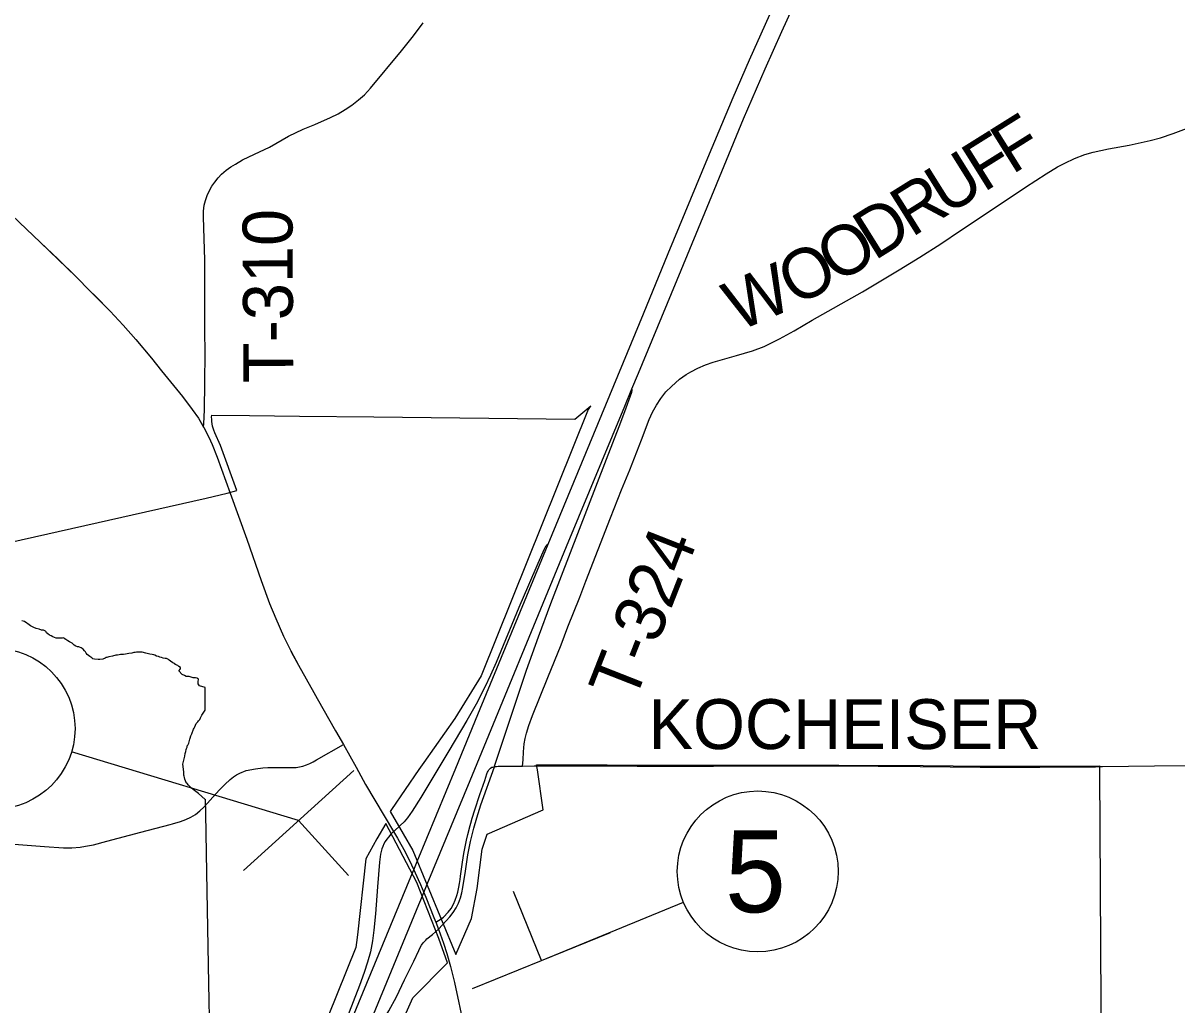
# Model space of a CAD drawing. Extents: x 40529 to 41139, y 15164 to 15584.
# Drawn here: x 40638.96 to 40678.43, y 15450.19 to 15483.78 of the extents above; entities that cross this region are included whole.
import ezdxf

# ---------------------------------------------------------------- set-up
doc = ezdxf.new("R2010")
doc.units = 0
for name, color, linetype in [('Default', 7, 'Continuous'), ('GM_X_Corporation', 7, 'Continuous'), ('GM_X_Interchange_Ramps', 7, 'Continuous'), ('GM_X_Interstate_Route', 7, 'Continuous'), ('GM_X_State_Route', 7, 'Continuous'), ('GM_X_Township_Road', 7, 'Continuous'), ('GM_X_Township_Road_Text', 7, 'Continuous'), ('SH_Data', 7, 'Continuous'), ('SH_Text', 7, 'Continuous')]:
    doc.layers.add(name, color=color, linetype=linetype)

msp = doc.modelspace()

# ---------------------------------------------------------------- linework, layer by layer
at = {"layer": 'Default'}
for p, q in [((40650.273, 15458.215), (40646.495, 15454.795)), ((40648.384, 15456.505), (40650.094, 15454.616)), ((40656.692, 15451.71), (40655.736, 15454.072)), ((40654.33, 15450.755), (40659.054, 15452.666))]:
    msp.add_line(p, q, dxfattribs=at)
at = {"layer": 'GM_X_Corporation'}
for points in [[(40636.703, 15465.612), (40641.064, 15466.592), (40645.217, 15467.526), (40645.936, 15467.698), (40646.266, 15467.787), (40645.71, 15469.328), (40645.521, 15469.763), (40645.486, 15469.849), (40645.462, 15469.922), (40645.442, 15469.997), (40645.427, 15470.073), (40645.416, 15470.149), (40645.41, 15470.226), (40645.408, 15470.303), (40645.409, 15470.372), (40646.701, 15470.358), (40648.408, 15470.339), (40650.952, 15470.311), (40657.836, 15470.236), (40658.382, 15470.685), (40658.362, 15470.659), (40658.289, 15470.562), (40654.63, 15461.454), (40653.728, 15459.986), (40652.668, 15458.491), (40652.612, 15458.411), (40652.497, 15458.244), (40651.558, 15456.884), (40651.516, 15456.806), (40651.958, 15456.045), (40652.287, 15455.479), (40653.766, 15451.922), (40654.181, 15452.883), (40654.295, 15453.146), (40654.49, 15454.177), (40654.657, 15455.523), (40654.837, 15456.038), (40656.747, 15456.867), (40656.558, 15458.233), (40656.521, 15458.402), (40656.787, 15458.404), (40658.001, 15458.405), (40658.935, 15458.404), (40660.055, 15458.399), (40662.669, 15458.396), (40664.805, 15458.4), (40666.858, 15458.399), (40669.747, 15458.387), (40671.796, 15458.362), (40673.846, 15458.359), (40675.779, 15458.376), (40675.78, 15458.189), (40675.845, 15446.277)], [(40645.447, 15443.901), (40645.314, 15450.925), (40645.241, 15454.724), (40645.203, 15456.743), (40645.194, 15457.227), (40645.189, 15457.221), (40644.958, 15457.428), (40644.817, 15457.533), (40644.719, 15457.61), (40644.685, 15457.638), (40644.617, 15457.706), (40644.574, 15457.767), (40644.537, 15457.794), (40644.533, 15457.802), (40644.511, 15457.86), (40644.492, 15457.919), (40644.482, 15457.973), (40644.467, 15458.02), (40644.461, 15458.054), (40644.458, 15458.164), (40644.427, 15458.43), (40644.491, 15458.705), (40644.498, 15458.798), (40644.523, 15458.862), (40644.536, 15458.933), (40644.546, 15458.96), (40644.566, 15459.011), (40644.57, 15459.054), (40644.591, 15459.08), (40644.623, 15459.145), (40644.661, 15459.286), (40644.674, 15459.317), (40644.693, 15459.4), (40644.728, 15459.467), (40644.792, 15459.621), (40644.811, 15459.661), (40644.837, 15459.708), (40644.882, 15459.816), (40644.884, 15459.83), (40644.897, 15459.844), (40644.933, 15459.875), (40644.96, 15459.912), (40645.002, 15459.96), (40645.031, 15460.016), (40645.077, 15460.103), (40645.18, 15460.279), (40645.184, 15461.057), (40644.988, 15461.104), (40644.946, 15461.182), (40644.948, 15461.271), (40644.958, 15461.315), (40644.96, 15461.332), (40644.958, 15461.342), (40644.925, 15461.359), (40644.911, 15461.368), (40644.901, 15461.368), (40644.856, 15461.379), (40644.837, 15461.38), (40644.776, 15461.381), (40644.674, 15461.416), (40644.642, 15461.425), (40644.6, 15461.426), (40644.534, 15461.432), (40644.48, 15461.464), (40644.403, 15461.491), (40644.282, 15461.619), (40644.339, 15461.69), (40644.34, 15461.712), (40644.338, 15461.731), (40644.287, 15461.772), (40644.254, 15461.807), (40644.159, 15461.838), (40644.158, 15461.862), (40644.08, 15461.896), (40643.994, 15461.958), (40643.955, 15461.992), (40643.928, 15462.009), (40643.862, 15462.045), (40643.819, 15462.047), (40643.745, 15462.054), (40643.687, 15462.074), (40643.637, 15462.091), (40643.587, 15462.109), (40643.524, 15462.126), (40643.467, 15462.154), (40643.431, 15462.165), (40643.367, 15462.177), (40643.293, 15462.194), (40643.205, 15462.217), (40643.153, 15462.228), (40643.027, 15462.26), (40642.888, 15462.263), (40642.838, 15462.259), (40642.789, 15462.253), (40642.751, 15462.246), (40642.681, 15462.229), (40642.577, 15462.214), (40642.462, 15462.193), (40642.388, 15462.185), (40642.336, 15462.184), (40642.292, 15462.179), (40642.242, 15462.169), (40642.182, 15462.163), (40642.131, 15462.161), (40642.013, 15462.124), (40641.893, 15462.097), (40641.819, 15462.078), (40641.801, 15462.077), (40641.762, 15462.051), (40641.682, 15462.025), (40641.581, 15462.015), (40641.524, 15462.013), (40641.404, 15462.016), (40641.345, 15462.034), (40641.306, 15462.062), (40641.236, 15462.115), (40641.194, 15462.145), (40641.144, 15462.177), (40641.109, 15462.23), (40641.089, 15462.267), (40641.062, 15462.303), (40641.008, 15462.358), (40640.973, 15462.386), (40640.947, 15462.408), (40640.889, 15462.436), (40640.86, 15462.443), (40640.818, 15462.445), (40640.758, 15462.463), (40640.709, 15462.495), (40640.683, 15462.526), (40640.661, 15462.542), (40640.637, 15462.566), (40640.592, 15462.589), (40640.546, 15462.613), (40640.492, 15462.644), (40640.456, 15462.67), (40640.421, 15462.697), (40640.365, 15462.733), (40640.346, 15462.752), (40640.308, 15462.743), (40640.247, 15462.737), (40640.091, 15462.74), (40639.97, 15462.786), (40639.913, 15462.814), (40639.859, 15462.845), (40639.802, 15462.883), (40639.763, 15462.926), (40639.742, 15462.956), (40639.721, 15462.976), (40639.695, 15462.993), (40639.651, 15463.008), (40639.585, 15463.017), (40639.507, 15463.046), (40639.403, 15463.072), (40639.328, 15463.1), (40639.215, 15463.166), (40639.122, 15463.227), (40639.088, 15463.257), (40639.009, 15463.305), (40638.917, 15463.338)], [(40652.057, 15449.92), (40652.294, 15450.437), (40653.477, 15451.638), (40653.182, 15452.468), (40652.425, 15454.379), (40651.362, 15456.401), (40651.058, 15455.875), (40650.678, 15455.196), (40650.395, 15452.588), (40650.367, 15452.326), (40650.337, 15452.153), (40647.478, 15445.056)]]:
    msp.add_lwpolyline(points, dxfattribs=at)
at = {"layer": 'GM_X_Interchange_Ramps'}
for points in [[(40653.167, 15452.781), (40653.427, 15453.071), (40653.557, 15453.206), (40653.673, 15453.352), (40653.772, 15453.51), (40653.854, 15453.678), (40653.919, 15453.853), (40653.968, 15454.033), (40654.006, 15454.216), (40654.087, 15454.771), (40654.176, 15455.325), (40654.266, 15455.783), (40654.373, 15456.238), (40654.475, 15456.597), (40654.618, 15457.042), (40655.08, 15458.342), (40655.087, 15458.362), (40656.182, 15461.64), (40656.584, 15462.787), (40657.009, 15463.924), (40658.918, 15468.859), (40659.347, 15469.976), (40659.543, 15470.492), (40659.777, 15471.152), (40659.788, 15471.198), (40659.791, 15471.222), (40659.789, 15471.241), (40659.787, 15471.264)], [(40656.924, 15465.953), (40656.903, 15465.947), (40656.875, 15465.928), (40656.858, 15465.911), (40656.834, 15465.878), (40656.786, 15465.782), (40656.567, 15465.29), (40656.248, 15464.557), (40655.92, 15463.789), (40655.139, 15461.904), (40654.951, 15461.479), (40654.751, 15461.061), (40654.452, 15460.485), (40654.135, 15459.918), (40653.52, 15458.88), (40652.567, 15457.29), (40652.269, 15456.82), (40652.109, 15456.593), (40651.988, 15456.455), (40651.854, 15456.327), (40651.647, 15456.143), (40651.631, 15456.129)], [(40651.631, 15456.129), (40651.539, 15456.034), (40651.455, 15455.932), (40651.4, 15455.859), (40651.347, 15455.782), (40651.302, 15455.701), (40651.263, 15455.617), (40651.231, 15455.53), (40651.183, 15455.35), (40651.144, 15455.074), (40651.084, 15454.236), (40651.014, 15453.307), (40650.959, 15452.75), (40650.91, 15452.381), (40650.839, 15452.015), (40650.743, 15451.655), (40650.629, 15451.3), (40650.47, 15450.862), (40649.894, 15449.386)], [(40652.731, 15452.411), (40652.774, 15452.458), (40652.96, 15452.598), (40653.167, 15452.781)], [(40648.174, 15443.15), (40648.194, 15443.161), (40648.21, 15443.173), (40648.231, 15443.19), (40648.254, 15443.227), (40648.351, 15443.428), (40648.385, 15443.492), (40648.582, 15443.906), (40648.844, 15444.505), (40649.716, 15446.574), (40650.058, 15447.343), (40650.38, 15448.018), (40650.717, 15448.686), (40650.986, 15449.178), (40651.47, 15449.989), (40651.732, 15450.474), (40652.01, 15451.055), (40652.32, 15451.696), (40652.492, 15452.061), (40652.54, 15452.158), (40652.585, 15452.233), (40652.645, 15452.319), (40652.731, 15452.411)]]:
    msp.add_lwpolyline(points, dxfattribs=at)
at = {"layer": 'GM_X_Interstate_Route'}
msp.add_line((40652.497, 15453.627), (40652.565, 15453.793), dxfattribs=at)
for points in [[(40652.785, 15454.324), (40654.247, 15457.87), (40657.549, 15465.872), (40659.548, 15470.678), (40659.787, 15471.264), (40660.006, 15471.801), (40661.47, 15475.331), (40662.356, 15477.487), (40663.605, 15480.503), (40664.341, 15482.217), (40664.908, 15483.496), (40667.468, 15489.094)], [(40648.136, 15444.675), (40648.586, 15445.785), (40652.223, 15454.578), (40652.322, 15454.819), (40652.439, 15455.101), (40653.759, 15458.293), (40654.516, 15460.125), (40656.924, 15465.953), (40660.178, 15473.833), (40661.026, 15475.903), (40662.384, 15479.173), (40663.245, 15481.238), (40663.802, 15482.52), (40664.754, 15484.647)], [(40652.565, 15453.793), (40652.665, 15454.035), (40652.785, 15454.324)], [(40641.19, 15426.749), (40641.685, 15427.752), (40641.91, 15428.229), (40642.242, 15428.931), (40642.782, 15430.119), (40643.263, 15431.23), (40644.049, 15433.124), (40645.472, 15436.571), (40645.814, 15437.405), (40648.174, 15443.15), (40648.376, 15443.642), (40652.497, 15453.627)]]:
    msp.add_lwpolyline(points, dxfattribs=at)
at = {"layer": 'GM_X_State_Route'}
for p, q in [((40649.647, 15459.571), (40649.914, 15459.097)), ((40649.914, 15459.097), (40650.348, 15458.324))]:
    msp.add_line(p, q, dxfattribs=at)
for points in [[(40631.547, 15483.816), (40633.184, 15482.292), (40635.219, 15480.375), (40636.374, 15479.292), (40639.551, 15476.277), (40640.161, 15475.701), (40640.758, 15475.114), (40641.268, 15474.603)], [(40641.268, 15474.603), (40641.417, 15474.454), (40641.939, 15473.924), (40642.383, 15473.447), (40642.814, 15472.958), (40643.349, 15472.313), (40643.695, 15471.887)], [(40643.695, 15471.887), (40644.405, 15471.01), (40644.743, 15470.566), (40644.953, 15470.26), (40645.134, 15469.962), (40645.145, 15469.943), (40645.315, 15469.614), (40645.428, 15469.36), (40645.599, 15468.927), (40646.042, 15467.699)], [(40646.042, 15467.699), (40646.61, 15466.122), (40647.102, 15464.715), (40647.39, 15463.926), (40647.601, 15463.407), (40647.868, 15462.811), (40648.115, 15462.308), (40648.144, 15462.253)], [(40648.144, 15462.253), (40648.378, 15461.814), (40648.905, 15460.885)], [(40648.905, 15460.885), (40649.022, 15460.679), (40649.647, 15459.571)], [(40650.348, 15458.324), (40650.665, 15457.737), (40651.631, 15456.129)], [(40651.631, 15456.129), (40651.766, 15455.9), (40652.036, 15455.408), (40652.244, 15454.99), (40652.322, 15454.819), (40652.477, 15454.481), (40652.547, 15454.313)], [(40652.547, 15454.313), (40652.665, 15454.035), (40652.731, 15453.878), (40653.01, 15453.184), (40653.075, 15453.025)], [(40653.075, 15453.025), (40653.167, 15452.781), (40653.336, 15452.309), (40653.454, 15451.955), (40653.581, 15451.505), (40653.711, 15450.959), (40654.051, 15449.411), (40654.584, 15446.816), (40654.633, 15446.578), (40654.89, 15445.299), (40655.141, 15444.113), (40655.453, 15442.666)]]:
    msp.add_lwpolyline(points, dxfattribs=at)
at = {"layer": 'GM_X_Township_Road'}
for p, q in [((40649.914, 15459.097), (40650.348, 15458.324)), ((40656.046, 15458.366), (40656.436, 15458.37))]:
    msp.add_line(p, q, dxfattribs=at)
for points in [[(40645.153, 15470.315), (40645.166, 15470.546), (40645.174, 15471.476), (40645.184, 15472.502), (40645.174, 15473.248), (40645.173, 15474.827), (40645.17, 15475.666), (40645.139, 15476.775), (40645.129, 15477.155), (40645.134, 15477.347), (40645.154, 15477.554), (40645.193, 15477.712), (40645.258, 15477.885), (40645.322, 15478.033), (40645.415, 15478.196), (40645.514, 15478.339), (40645.632, 15478.482), (40645.746, 15478.61), (40645.909, 15478.748), (40646.069, 15478.857), (40646.224, 15478.959), (40646.464, 15479.098), (40646.876, 15479.296), (40647.384, 15479.538), (40648.034, 15479.91), (40648.538, 15480.149), (40648.943, 15480.312), (40649.479, 15480.554), (40649.73, 15480.679), (40649.972, 15480.82), (40650.204, 15480.977), (40650.427, 15481.151), (40650.64, 15481.323), (40650.847, 15481.555), (40651.901, 15482.83), (40652.312, 15483.338), (40652.649, 15483.784)], [(40656.046, 15458.366), (40656.059, 15458.574), (40656.075, 15458.848), (40656.102, 15459.124), (40656.134, 15459.306), (40656.178, 15459.485), (40656.26, 15459.75), (40656.389, 15460.098), (40656.903, 15461.396), (40657.362, 15462.516), (40657.596, 15463.124), (40658.002, 15464.143), (40658.212, 15464.69), (40659.049, 15466.861), (40659.423, 15467.809), (40659.709, 15468.493), (40660.116, 15469.529), (40660.377, 15470.217), (40660.494, 15470.474), (40660.621, 15470.708), (40660.778, 15470.943), (40660.948, 15471.162), (40661.138, 15471.352), (40661.272, 15471.478), (40661.414, 15471.596), (40661.639, 15471.757), (40661.796, 15471.852), (40662.043, 15471.977), (40662.299, 15472.086), (40662.56, 15472.178), (40663.365, 15472.409), (40663.906, 15472.571), (40664.305, 15472.722), (40664.836, 15472.978), (40665.334, 15473.255), (40665.951, 15473.617), (40667.677, 15474.581), (40668.931, 15475.338), (40669.64, 15475.776), (40670.352, 15476.233), (40671.028, 15476.679), (40671.704, 15477.131), (40673.252, 15478.166), (40673.952, 15478.624), (40674.349, 15478.864), (40674.596, 15478.99), (40674.921, 15479.153), (40675.276, 15479.286), (40675.567, 15479.365), (40676.089, 15479.474), (40676.8, 15479.607), (40677.509, 15479.76), (40677.864, 15479.859), (40678.305, 15480.007), (40679.613, 15480.497)], [(40645.134, 15469.962), (40645.14, 15470.07), (40645.153, 15470.315)], [(40648.22, 15458.313), (40648.294, 15458.318), (40648.41, 15458.336), (40648.527, 15458.36), (40648.657, 15458.405), (40648.762, 15458.45), (40648.876, 15458.51), (40648.996, 15458.579), (40649.914, 15459.097)], [(40645.772, 15457.648), (40645.858, 15457.738), (40646.036, 15457.904), (40646.153, 15457.996), (40646.256, 15458.062), (40646.367, 15458.121), (40646.588, 15458.207), (40646.906, 15458.273), (40647.162, 15458.304), (40647.327, 15458.312), (40647.549, 15458.316), (40648.195, 15458.311), (40648.22, 15458.313)], [(40650.348, 15458.324), (40650.665, 15457.737), (40651.631, 15456.129)], [(40653.075, 15453.025), (40653.255, 15453.135), (40653.335, 15453.197), (40653.496, 15453.37), (40653.6, 15453.497), (40653.685, 15453.638), (40653.743, 15453.777), (40653.797, 15453.933), (40653.831, 15454.048), (40653.869, 15454.219), (40653.892, 15454.345), (40653.909, 15454.483), (40653.925, 15454.602), (40653.99, 15455.075), (40654.038, 15455.373), (40654.127, 15455.831), (40654.175, 15456.025), (40654.247, 15456.331), (40654.269, 15456.411), (40654.318, 15456.581), (40654.406, 15456.866), (40654.58, 15457.391), (40654.749, 15457.868), (40654.827, 15458.097), (40654.85, 15458.155), (40654.87, 15458.193), (40654.893, 15458.23), (40654.92, 15458.266), (40654.95, 15458.296), (40654.989, 15458.321), (40655.028, 15458.332), (40655.08, 15458.342)], [(40655.08, 15458.342), (40655.101, 15458.345), (40655.153, 15458.352), (40655.214, 15458.357), (40655.338, 15458.362), (40655.375, 15458.362), (40655.863, 15458.365), (40656.046, 15458.366)], [(40656.436, 15458.37), (40656.702, 15458.372), (40657.914, 15458.373), (40658.847, 15458.371), (40659.966, 15458.366), (40662.578, 15458.364), (40664.712, 15458.367), (40666.762, 15458.367), (40669.649, 15458.354), (40671.696, 15458.33), (40673.743, 15458.327), (40675.645, 15458.343)], [(40675.645, 15458.343), (40675.674, 15458.344), (40675.886, 15458.345), (40677.657, 15458.374), (40680.824, 15458.401), (40681.998, 15458.42), (40682.252, 15458.425)], [(40645.159, 15456.979), (40645.555, 15457.414), (40645.686, 15457.558), (40645.772, 15457.648)], [(40644.066, 15456.386), (40644.342, 15456.469), (40644.519, 15456.534), (40644.69, 15456.614), (40644.852, 15456.712), (40645.001, 15456.829), (40645.139, 15456.957), (40645.159, 15456.979)], [(40637.457, 15455.78), (40639.689, 15455.612), (40640.342, 15455.571), (40640.623, 15455.57), (40640.904, 15455.591), (40641.09, 15455.619), (40641.365, 15455.675), (40641.818, 15455.791), (40642.99, 15456.101), (40643.983, 15456.361), (40644.066, 15456.386)], [(40651.631, 15456.129), (40651.766, 15455.9), (40652.036, 15455.408), (40652.244, 15454.99), (40652.322, 15454.819), (40652.477, 15454.481), (40652.547, 15454.313)], [(40652.547, 15454.313), (40652.665, 15454.035), (40652.731, 15453.878), (40653.01, 15453.184), (40653.075, 15453.025)]]:
    msp.add_lwpolyline(points, dxfattribs=at)
at = {"layer": 'SH_Data'}
for p, q in [((40648.384, 15456.505), (40640.615, 15458.851)), ((40656.692, 15451.71), (40661.546, 15453.713))]:
    msp.add_line(p, q, dxfattribs=at)
msp.add_lwpolyline([(40636.374, 15479.292), (40639.551, 15476.277), (40640.758, 15475.114), (40641.268, 15474.603), (40641.939, 15473.924), (40642.383, 15473.447), (40642.814, 15472.958), (40643.349, 15472.313), (40643.695, 15471.887), (40644.405, 15471.01), (40644.743, 15470.566), (40644.953, 15470.26), (40645.143, 15469.947), (40645.315, 15469.614), (40645.428, 15469.36), (40645.599, 15468.927), (40646.042, 15467.699), (40646.61, 15466.122), (40647.102, 15464.715), (40647.39, 15463.926), (40647.601, 15463.407), (40647.868, 15462.811), (40648.115, 15462.308), (40648.378, 15461.814), (40648.905, 15460.885), (40649.022, 15460.679), (40649.647, 15459.571), (40649.914, 15459.097), (40650.348, 15458.324), (40650.665, 15457.737), (40651.631, 15456.129), (40651.766, 15455.9), (40652.036, 15455.408), (40652.244, 15454.99), (40652.322, 15454.819), (40652.477, 15454.481), (40652.547, 15454.313), (40652.665, 15454.035), (40652.731, 15453.878), (40653.01, 15453.184), (40653.075, 15453.025), (40653.167, 15452.781), (40653.336, 15452.309), (40653.454, 15451.955), (40653.581, 15451.505), (40653.711, 15450.959), (40654.051, 15449.411)], dxfattribs=at)
at = {"layer": 'SH_Text'}
for centre in [(40637.983, 15459.646), (40664.088, 15454.762)]:
    msp.add_circle(centre, 2.75, dxfattribs=at)

# ---------------------------------------------------------------- texts
at = {"layer": 'GM_X_Township_Road_Text'}
for s, height, rotation, p in [('F', 1.706, 32.0386, (40672.789, 15478.581)), ('F', 1.706, 32.0426, (40671.813, 15477.97)), ('U', 1.706, 32.044, (40670.54, 15477.174)), ('R', 1.706, 32.0432, (40669.353, 15476.43)), ('D', 1.706, 32.0398, (40668.08, 15475.634)), ('T-310', 1.7063, 90.2854, (40648.2, 15471.466)), ('O', 1.706, 31.9826, (40666.804, 15474.837)), ('O', 1.706, 28.4967, (40665.387, 15474.064)), ('W', 1.706, 23.0155, (40663.407, 15473.213)), ('T-324', 1.7063, 68.5618, (40659.856, 15460.494)), ('KOCHEISER', 1.7063, 0, (40660.354, 15458.946))]:
    msp.add_text(s, height=height, rotation=rotation, dxfattribs=at).set_placement(p)
at = {"layer": 'SH_Text'}
msp.add_text('5', height=2.8, dxfattribs=at).set_placement((40662.969, 15453.362))

doc.saveas('drawing.dxf')
